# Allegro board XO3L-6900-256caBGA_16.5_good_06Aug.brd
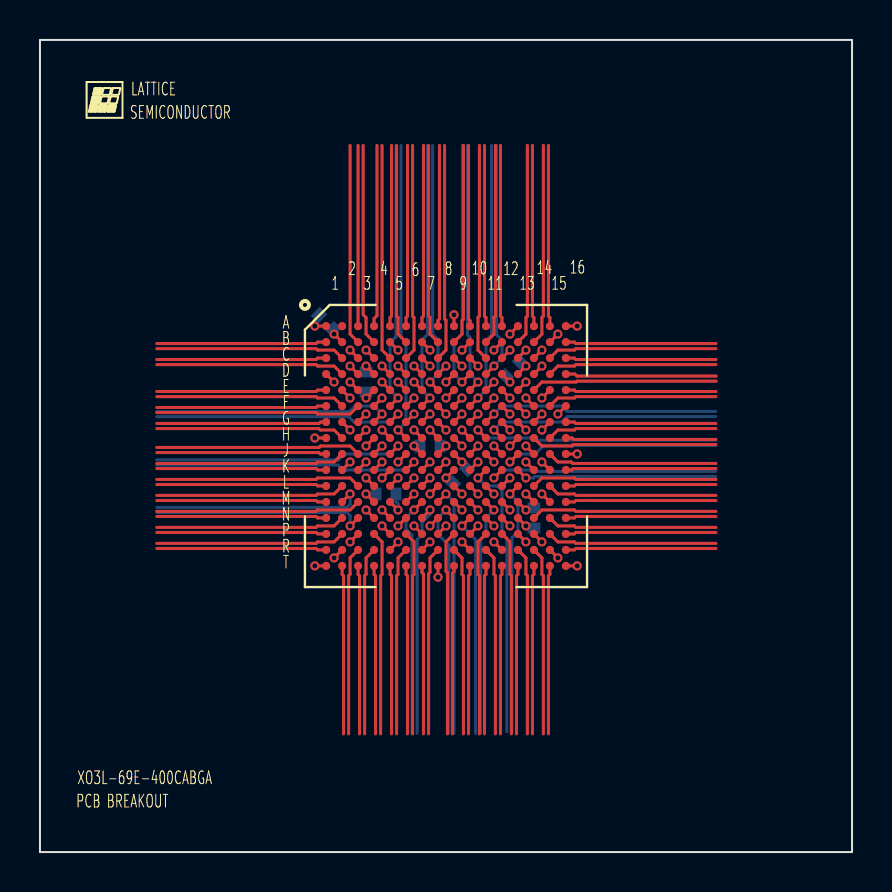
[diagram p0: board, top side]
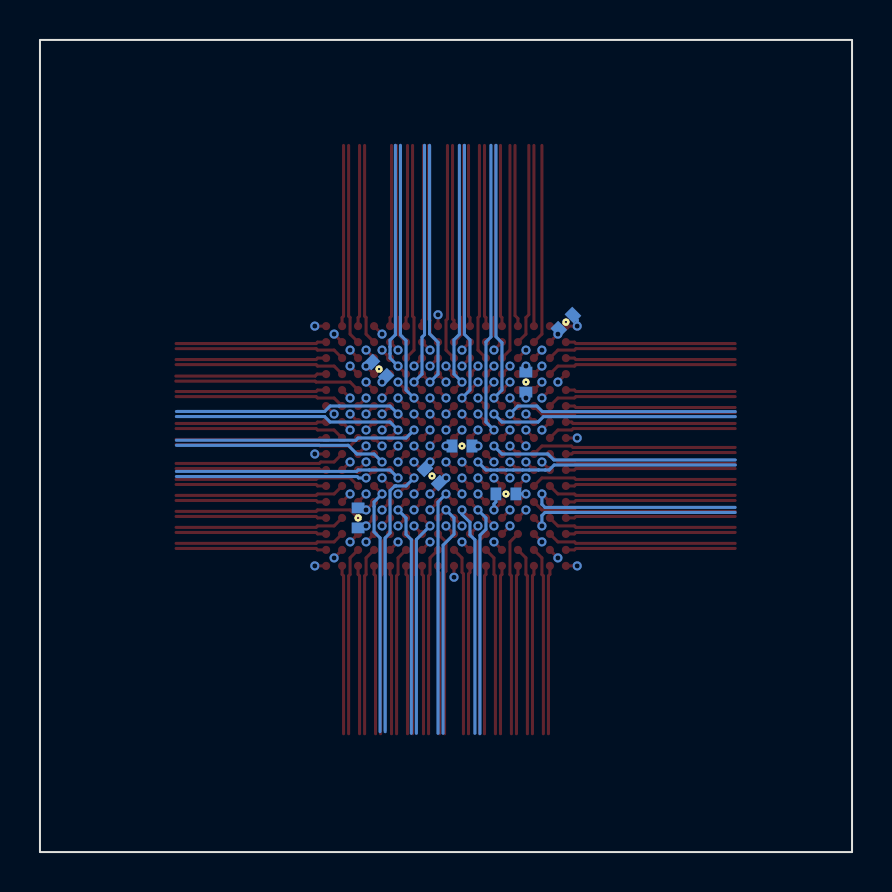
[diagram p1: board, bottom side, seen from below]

Outline 40.64 x 40.64 mm; copper layers: TOP, L2_GND, L3_SIGNAL, L4_SIGNAL, L5_PWR, BOTTOM. Coordinates in mm from the lower left corner of the outline.
Outline path: rectangle 0,0 40.64,40.64

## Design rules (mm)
net group CDPB4: nets PB4C PB4D
net group CDPB13: nets PB13C PB13D
net group CDPB18: nets PB18C PB18D
net group CDPB26: nets PB26C PB26D
net group CDPB31: nets PB31C PB31D
net group CDPB38: nets PB38C PB38D
net group CDPL2: nets PL2C PL2D
net group CDPL4: nets PL4C PL4D
net group CDPL6: nets PL6C PL6D
net group CDPL7: nets PL7C PL7D
net group CDPL9: nets PL9C PL9D
net group CDPL10: nets PL10C PL10D
net group CDPL15: nets PL15C PL15D
net group CDPL16: nets PL16C PL16D
net group CDPL19: nets PL19C PL19D
net group CDPL21: nets PL21C PL21D
net group CDPL23: nets PL23C PL23D
net group CDPL25: nets PL25C PL25D
net group CDPR2: nets PR2C PR2D
net group CDPR4: nets PR4C PR4D
net group CDPR6: nets PR6C PR6D
net group CDPR7: nets PR7C PR7D
net group CDPR10: nets PR10C PR10D
net group CDPR11: nets PR11C PR11D
net group CDPR16: nets PR16C PR16D
net group CDPR17: nets PR17C PR17D
net group CDPR19: nets PR19C PR19D
net group CDPR21: nets PR21C PR21D
net group CDPR23: nets PR23C PR23D
net group CDPR25: nets PR25C PR25D
net group CDPT14: nets PT14C PT14D
net group CDPT17: nets PT17C PT17D
net group CDPT22: nets PT22C PT22D
net group CDPT27: nets PT27C PT27D
net group CDPT36: nets PT36C PT36D
net group PB4: nets PB4A PB4B
net group PB6: nets PB6A PB6B
net group PB7: nets PB7A PB7B
net group PB9: nets PB9A PB9B
net group PB10: nets PB10A PB10B
net group PB12: nets PB12A PB12B
net group PB13: nets PB13A PB13B
net group PB15: nets PB15A PB15B
net group PB16: nets PB16A PB16B
net group PB18: nets PB18A PB18B
net group PB21: nets PB21A PB21B
net group PB23: nets PB23A PB23B
net group PB26: nets PB26A PB26B
net group PB28: nets PB28A PB28B
net group PB29: nets PB29A PB29B
net group PB31: nets PB31A PB31B
net group PB34: nets PB34A PB34B
net group PB35: nets PB35A PB35B
net group PB37: nets PB37A PB37B
net group PB38: nets PB38A PB38B
net group PL3: nets PL3A PL3B
net group PL4: nets PL4A PL4B
net group PL6: nets PL6A PL6B
net group PL8: nets PL8A PL8B
net group PL9: nets PL9A PL9B
net group PL10: nets PL10A PL10B
net group PL11: nets PL11A PL11B
net group PL12: nets PL12A PL12B
net group PL15: nets PL15A PL15B
net group PL17: nets PL17A PL17B
net group PL19: nets PL19A PL19B
net group PL22: nets PL22A PL22B
net group PL24: nets PL24A PL24B
net group PL25: nets PL25A PL25B
net group PR2: nets PR2A PR2B
net group PR3: nets PR3A PR3B
net group PR5: nets PR5A PR5B
net group PR7: nets PR7A PR7B
net group PR9: nets PR9A PR9B
net group PR11: nets PR11A PR11B
net group PR12: nets PR12A PR12B
net group PR15: nets PR15A PR15B
net group PR16: nets PR16A PR16B
net group PR17: nets PR17A PR17B
net group PR18: nets PR18A PR18B
net group PR21: nets PR21A PR21B
net group PR23: nets PR23A PR23B
net group PR24: nets PR24A PR24B
net group PT9: nets PT9A PT9B
net group PT10: nets PT10A PT10B
net group PT11: nets PT11A PT11B
net group PT12: nets PT12A PT12B
net group PT14: nets PT14A PT14B
net group PT15: nets PT15A PT15B
net group PT16: nets PT16A PT16B
net group PT17: nets PT17A PT17B
net group PT18: nets PT18A PT18B
net group PT21: nets PT21A PT21B
net group PT22: nets PT22A PT22B
net group PT25: nets PT25A PT25B
net group PT26: nets PT26A PT26B
net group PT27: nets PT27A PT27B
net group PT28: nets PT28A PT28B
net group PT32: nets PT32A PT32B
net group PT33: nets PT33A PT33B
net group PT34: nets PT34A PT34B
net group PT35: nets PT35A PT35B
net group PT36: nets PT36A PT36B

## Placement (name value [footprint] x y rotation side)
BGA  -  [BGA256C80P16X16_1400X1400X17-1]  20.32 20.32 270 top
C1  VAL  [C0402]  16.32 23.52 90 bottom
C2  VAL  [C0402]  23.67 24.17 45 bottom
C3  VAL  [C0402]  14.32 26.52 315 bottom
C4  VAL  [C0402]  19.52 20.32 0 bottom
C5  VAL  [C0402]  24.72 16.72 270 bottom
C6  VAL  [C0402]  21.02 18.82 45 bottom
C7  VAL  [C0402]  17.32 17.92 0 bottom
NOREF  -  []  24.69 13 0 top

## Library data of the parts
BGA = BGA256C80P16X16_1400X1400X17-1
C1-C7 = C0402: User Part Number: UPN; Tolerance: TOL

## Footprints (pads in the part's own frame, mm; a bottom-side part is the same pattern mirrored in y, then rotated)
BGA256C80P16X16_1400X1400X17-1
  round 0.406 smd: A1(-6,-6) A2(-6,-5.2) A3(-6,-4.4) A4(-6,-3.6) A5(-6,-2.8) A6(-6,-2) A7(-6,-1.2) A8(-6,-0.4) A9(-6,0.4) A10(-6,1.2) A11(-6,2) A12(-6,2.8) A13(-6,3.6) A14(-6,4.4) A15(-6,5.2) A16(-6,6) B1(-5.2,-6) B2(-5.2,-5.2) B3(-5.2,-4.4) B4(-5.2,-3.6) B5(-5.2,-2.8) B6(-5.2,-2) B7(-5.2,-1.2) B8(-5.2,-0.4) B9(-5.2,0.4) B10(-5.2,1.2) B11(-5.2,2) B12(-5.2,2.8) B13(-5.2,3.6) B14(-5.2,4.4) B15(-5.2,5.2) B16(-5.2,6) C1(-4.4,-6) C2(-4.4,-5.2) C3(-4.4,-4.4) C4(-4.4,-3.6) C5(-4.4,-2.8) C6(-4.4,-2) C7(-4.4,-1.2) C8(-4.4,-0.4) C9(-4.4,0.4) C10(-4.4,1.2) C11(-4.4,2) C12(-4.4,2.8) C13(-4.4,3.6) C14(-4.4,4.4) C15(-4.4,5.2) C16(-4.4,6) D1(-3.6,-6) D2(-3.6,-5.2) D3(-3.6,-4.4) D4(-3.6,-3.6) D5(-3.6,-2.8) D6(-3.6,-2) D7(-3.6,-1.2) D8(-3.6,-0.4) D9(-3.6,0.4) D10(-3.6,1.2) D11(-3.6,2) D12(-3.6,2.8) D13(-3.6,3.6) D14(-3.6,4.4) D15(-3.6,5.2) D16(-3.6,6) E1(-2.8,-6) E2(-2.8,-5.2) E3(-2.8,-4.4) E4(-2.8,-3.6) E5(-2.8,-2.8) E6(-2.8,-2) E7(-2.8,-1.2) E8(-2.8,-0.4) E9(-2.8,0.4) E10(-2.8,1.2) E11(-2.8,2) E12(-2.8,2.8) E13(-2.8,3.6) E14(-2.8,4.4) E15(-2.8,5.2) E16(-2.8,6) F1(-2,-6) F2(-2,-5.2) F3(-2,-4.4) F4(-2,-3.6) F5(-2,-2.8) F6(-2,-2) F7(-2,-1.2) F8(-2,-0.4) F9(-2,0.4) F10(-2,1.2) F11(-2,2) F12(-2,2.8) F13(-2,3.6) F14(-2,4.4) F15(-2,5.2) F16(-2,6) G1(-1.2,-6) G2(-1.2,-5.2) G3(-1.2,-4.4) G4(-1.2,-3.6) G5(-1.2,-2.8) G6(-1.2,-2) G7(-1.2,-1.2) G8(-1.2,-0.4) G9(-1.2,0.4) G10(-1.2,1.2) G11(-1.2,2) G12(-1.2,2.8) G13(-1.2,3.6) G14(-1.2,4.4) G15(-1.2,5.2) G16(-1.2,6) H1(-0.4,-6) H2(-0.4,-5.2) H3(-0.4,-4.4) H4(-0.4,-3.6) H5(-0.4,-2.8) H6(-0.4,-2) H7(-0.4,-1.2) H8(-0.4,-0.4) H9(-0.4,0.4) H10(-0.4,1.2) H11(-0.4,2) H12(-0.4,2.8) H13(-0.4,3.6) H14(-0.4,4.4) H15(-0.4,5.2) H16(-0.4,6) J1(0.4,-6) J2(0.4,-5.2) J3(0.4,-4.4) J4(0.4,-3.6) J5(0.4,-2.8) J6(0.4,-2) J7(0.4,-1.2) J8(0.4,-0.4) J9(0.4,0.4) J10(0.4,1.2) J11(0.4,2) J12(0.4,2.8) J13(0.4,3.6) J14(0.4,4.4) J15(0.4,5.2) J16(0.4,6) K1(1.2,-6) K2(1.2,-5.2) K3(1.2,-4.4) K4(1.2,-3.6) K5(1.2,-2.8) K6(1.2,-2) K7(1.2,-1.2) K8(1.2,-0.4) K9(1.2,0.4) K10(1.2,1.2) K11(1.2,2) K12(1.2,2.8) K13(1.2,3.6) K14(1.2,4.4) K15(1.2,5.2) K16(1.2,6) L1(2,-6) L2(2,-5.2) L3(2,-4.4) L4(2,-3.6) L5(2,-2.8) L6(2,-2) L7(2,-1.2) L8(2,-0.4) L9(2,0.4) L10(2,1.2) L11(2,2) L12(2,2.8) L13(2,3.6) L14(2,4.4) L15(2,5.2) L16(2,6) M1(2.8,-6) M2(2.8,-5.2) M3(2.8,-4.4) M4(2.8,-3.6) M5(2.8,-2.8) M6(2.8,-2) M7(2.8,-1.2) M8(2.8,-0.4) M9(2.8,0.4) M10(2.8,1.2) M11(2.8,2) M12(2.8,2.8) M13(2.8,3.6) M14(2.8,4.4) M15(2.8,5.2) M16(2.8,6) N1(3.6,-6) N2(3.6,-5.2) N3(3.6,-4.4) N4(3.6,-3.6) N5(3.6,-2.8) N6(3.6,-2) N7(3.6,-1.2) N8(3.6,-0.4) N9(3.6,0.4) N10(3.6,1.2) N11(3.6,2) N12(3.6,2.8) N13(3.6,3.6) N14(3.6,4.4) N15(3.6,5.2) N16(3.6,6) P1(4.4,-6) P2(4.4,-5.2) P3(4.4,-4.4) P4(4.4,-3.6) P5(4.4,-2.8) P6(4.4,-2) P7(4.4,-1.2) P8(4.4,-0.4) P9(4.4,0.4) P10(4.4,1.2) P11(4.4,2) P12(4.4,2.8) P13(4.4,3.6) P14(4.4,4.4) P15(4.4,5.2) P16(4.4,6) R1(5.2,-6) R2(5.2,-5.2) R3(5.2,-4.4) R4(5.2,-3.6) R5(5.2,-2.8) R6(5.2,-2) R7(5.2,-1.2) R8(5.2,-0.4) R9(5.2,0.4) R10(5.2,1.2) R11(5.2,2) R12(5.2,2.8) R13(5.2,3.6) R14(5.2,4.4) R15(5.2,5.2) R16(5.2,6) T1(6,-6) T2(6,-5.2) T3(6,-4.4) T4(6,-3.6) T5(6,-2.8) T6(6,-2) T7(6,-1.2) T8(6,-0.4) T9(6,0.4) T10(6,1.2) T11(6,2) T12(6,2.8) T13(6,3.6) T14(6,4.4) T15(6,5.2) T16(6,6)
C0402
  rect 0.54x0.64 smd: 1(-0.5,0) 2(0.5,0)

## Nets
GND: BGA.B2 BGA.B15 BGA.C3 BGA.C14 BGA.D4 BGA.D13 BGA.E5 BGA.E12 BGA.F6 BGA.F11 BGA.H8 BGA.H9 BGA.J8 BGA.J9 BGA.L6 BGA.L11 BGA.M5 BGA.M12 BGA.N4 BGA.N13 BGA.P3 BGA.P14 BGA.R2 BGA.R15 C1.2 C2.2 C3.2 C4.2 C5.2 C6.2 C7.2
VCC: BGA.A1 BGA.A16 BGA.G7 BGA.G10 BGA.K7 BGA.K10 BGA.T1 BGA.T16 C3.1
VCCIO0: BGA.D5 BGA.D12 BGA.G8 BGA.G9 C2.1
VCCIO1: BGA.E13 BGA.H10 BGA.J10 BGA.M13 C5.1
VCCIO2: BGA.K8 BGA.K9 BGA.N5 BGA.N12 C6.1
VCCIO3: BGA.M4 C7.1
VCCIO4: BGA.H7 BGA.J7 C4.1
VCCIO5: BGA.E4 C1.1
NC: BGA.A2
PB4A: BGA.P4
PB4B: BGA.T4
PB4C: BGA.T2
PB4D: BGA.R3
PB6A: BGA.R5
PB6B: BGA.P5
PB7A: BGA.T3
PB7B: BGA.R4
PB9A: BGA.T5
PB9B: BGA.R6
PB10A: BGA.N6
PB10B: BGA.L7
PB12A: BGA.P6
PB12B: BGA.T6
PB13A: BGA.R7
PB13B: BGA.P7
PB13C: BGA.M7
PB13D: BGA.N7
PB15A: BGA.M6
PB15B: BGA.L8
PB16A: BGA.T7
PB16B: BGA.R8
PB18A: BGA.P8
PB18B: BGA.T8
PB18C: BGA.N8
PB18D: BGA.L9
PB21A: BGA.M8
PB21B: BGA.N9
PB23A: BGA.T9
PB23B: BGA.P9
PB26A: BGA.R9
PB26B: BGA.T10
PB26C: BGA.M9
PB26D: BGA.L10
PB28A: BGA.N10
PB28B: BGA.M11
PB29A: BGA.P10
PB29B: BGA.R10
PB31A: BGA.T11
PB31B: BGA.P11
PB31C: BGA.M10
PB31D: BGA.N11
PB34A: BGA.R13
PB34B: BGA.T14
PB35A: BGA.R11
PB35B: BGA.T12
PB37A: BGA.P12
PB37B: BGA.T13
PB38A: BGA.R12
PB38B: BGA.P13
PB38C: BGA.T15
PB38D: BGA.R14
PL2C: BGA.B1
PL2D: BGA.C2
PL3A: BGA.D3
PL3B: BGA.D1
PL4A: BGA.E2
PL4B: BGA.E3
PL4C: BGA.C1
PL4D: BGA.D2
PL6A: BGA.E1
PL6B: BGA.F2
PL6C: BGA.F4
PL6D: BGA.G6
PL7C: BGA.G5
PL7D: BGA.G4
PL8A: BGA.F3
PL8B: BGA.F1
PL9A: BGA.G2
PL9B: BGA.G3
PL9C: BGA.F5
PL9D: BGA.H6
PL10A: BGA.G1
PL10B: BGA.H2
PL10C: BGA.H4
PL10D: BGA.J6
PL11A: BGA.H3
PL11B: BGA.H1
PL12A: BGA.J1
PL12B: BGA.J3
PL15A: BGA.J2
PL15B: BGA.K1
PL15C: BGA.H5
PL15D: BGA.J4
PL16C: BGA.J5
PL16D: BGA.K6
PL17A: BGA.K3
PL17B: BGA.K2
PL19A: BGA.L1
PL19B: BGA.L3
PL19C: BGA.K4
PL19D: BGA.L5
PL21C: BGA.K5
PL21D: BGA.L4
PL22A: BGA.L2
PL22B: BGA.M1
PL23C: BGA.N2
PL23D: BGA.P1
PL24A: BGA.M3
PL24B: BGA.N1
PL25A: BGA.M2
PL25B: BGA.N3
PL25C: BGA.R1
PL25D: BGA.P2
PR2A: BGA.D14
PR2B: BGA.E15
PR2C: BGA.C15
PR2D: BGA.B16
PR3A: BGA.D16
PR3B: BGA.E14
PR4C: BGA.C16
PR4D: BGA.D15
PR5A: BGA.E16
PR5B: BGA.F15
PR6C: BGA.F13
PR6D: BGA.G12
PR7A: BGA.F14
PR7B: BGA.F16
PR7C: BGA.F12
PR7D: BGA.G13
PR9A: BGA.G15
PR9B: BGA.G14
PR10C: BGA.G11
PR10D: BGA.H12
PR11A: BGA.G16
PR11B: BGA.H15
PR11C: BGA.H13
PR11D: BGA.J12
PR12A: BGA.H14
PR12B: BGA.H16
PR15A: BGA.J16
PR15B: BGA.J14
PR16A: BGA.J15
PR16B: BGA.K16
PR16C: BGA.H11
PR16D: BGA.J13
PR17A: BGA.K14
PR17B: BGA.K15
PR17C: BGA.J11
PR17D: BGA.L12
PR18A: BGA.L16
PR18B: BGA.L14
PR19C: BGA.K13
PR19D: BGA.K12
PR21A: BGA.L15
PR21B: BGA.M16
PR21C: BGA.K11
PR21D: BGA.L13
PR23A: BGA.M14
PR23B: BGA.M15
PR23C: BGA.N15
PR23D: BGA.P16
PR24A: BGA.N16
PR24B: BGA.N14
PR25C: BGA.P15
PR25D: BGA.R16
PT9A: BGA.C4
PT9B: BGA.B5
PT9C: BGA.B3
PT10A: BGA.A4
PT10B: BGA.C5
PT11A: BGA.A5
PT11B: BGA.B6
PT12A: BGA.A3
PT12B: BGA.B4
PT14A: BGA.D6
PT14B: BGA.E7
PT14C: BGA.C6
PT14D: BGA.A6
PT15A: BGA.B7
PT15B: BGA.C7
PT16A: BGA.E6
PT16B: BGA.D7
PT17A: BGA.F7
PT17B: BGA.E8
PT17C: BGA.A7
PT17D: BGA.B8
PT18A: BGA.C8
PT18B: BGA.A8
PT21A: BGA.D8
PT21B: BGA.E9
PT22A: BGA.F8
PT22B: BGA.D9
PT22C: BGA.A9
PT22D: BGA.C9
PT25A: BGA.B9
PT25B: BGA.A10
PT26A: BGA.F9
PT26B: BGA.E11
PT27A: BGA.D10
PT27B: BGA.E10
PT27C: BGA.C10
PT27D: BGA.B10
PT28A: BGA.A11
PT28B: BGA.C11
PT32A: BGA.F10
PT32B: BGA.D11
PT33A: BGA.B11
PT33B: BGA.A12
PT34A: BGA.B13
PT34B: BGA.A14
PT35A: BGA.C12
PT35B: BGA.B12
PT36A: BGA.B14
PT36B: BGA.A15
PT36C: BGA.A13
PT36D: BGA.C13

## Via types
v1: diameter 0.457, hole 0.254, TOP to BOTTOM, 158 vias

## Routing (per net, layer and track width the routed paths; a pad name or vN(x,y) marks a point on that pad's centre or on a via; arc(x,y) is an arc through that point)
GND: length 16.6
  TOP w0.152: v1(24.32,16.32) BGA.N13 ; v1(22.72,22.72) BGA.F11 ; v1(22.72,17.92) BGA.L11 ; v1(19.52,21.12) BGA.H8 ; v1(16.32,17.12) BGA.N4 ; v1(25.12,25.12) BGA.C14 ; v1(14.72,14.72) BGA.R2 ; v1(17.12,23.52) BGA.E5 ; v1(25.92,25.92) BGA.B15 ; v1(18.72,18.72) BGA.L6 ; v1(15.52,25.12) BGA.C3 ; v1(15.52,15.52) BGA.P3 ; v1(23.52,22.72) BGA.E12 ; v1(21.12,19.52) BGA.J9 ; v1(25.92,14.72) BGA.R15 ; v1(20.32,20.32) BGA.J8 ; v1(21.12,20.32) BGA.H9 ; v1(25.12,15.52) BGA.P14 ; BGA.M5 v1(17.92,17.12) ; v1(16.32,24.32) BGA.D4 ; v1(14.72,25.92) BGA.B2 ; v1(18.72,22.72) BGA.F6 ; v1(24.32,24.32) BGA.D13 ; v1(23.52,17.12) BGA.M12
  BOTTOM w0.152: C7.2 17.82,17.52 17.92,17.43 v1(17.92,17.12) ; C1.2 v1(16.32,24.32) ; C4.2 v1(20.32,20.32) ; v1(24.32,24.32) 24.12,24.52 C2.2 ; C3.2 14.72,26.12 v1(14.72,25.92) ; v1(24.32,16.32) 24.62,16.32 C5.2 ; v1(21.12,19.52) 21.37,19.27 C6.2
VCC: length 5.2
  TOP w0.152: v1(13.75,14.32) BGA.T1 ; v1(26.89,26.32) BGA.A16 ; v1(21.92,19.52) BGA.K10 ; v1(21.92,21.92) BGA.G10 ; v1(13.75,26.32) BGA.A1 ; v1(19.52,21.92) BGA.G7 ; v1(19.52,19.52) BGA.K7 ; v1(26.89,14.32) BGA.T16
  BOTTOM w0.152: v1(13.75,26.32) 13.75,26.62 13.97,26.84 C3.1
VCCIO0: length 2.6
  TOP w0.152: v1(23.52,23.52) BGA.D12 ; v1(20.32,21.12) BGA.G8 ; v1(21.12,21.92) BGA.G9 ; v1(17.12,24.32) BGA.D5
  BOTTOM w0.152: v1(23.52,23.52) 23.32,23.72 C2.1
VCCIO1: length 2.7
  TOP w0.152: v1(24.32,23.52) BGA.E13 ; v1(21.92,20.32) BGA.J10 ; v1(21.12,21.12) BGA.H10 ; v1(24.32,17.12) BGA.M13
  BOTTOM w0.152: C5.1 24.72,17.18 24.66,17.12 v1(24.32,17.12)
VCCIO2: length 2.7
  TOP w0.152: v1(17.12,17.12) BGA.N5 ; BGA.K9 v1(20.32,18.72) ; v1(20.32,19.52) BGA.K8 ; v1(23.52,16.32) BGA.N12
  BOTTOM w0.152: C6.1 20.57,18.47 v1(20.32,18.72)
VCCIO3: length 1.1
  TOP w0.152: BGA.M4 v1(16.32,17.92)
  BOTTOM w0.152: v1(16.32,17.92) C7.1
VCCIO4: length 1.4
  TOP w0.152: v1(18.72,20.32) BGA.J7 ; v1(18.72,21.12) BGA.H7
  BOTTOM w0.152: C4.1 v1(18.72,20.32)
VCCIO5: length 0.9
  TOP w0.152: v1(16.32,22.72) BGA.E4
  BOTTOM w0.152: C1.1 v1(16.32,22.72)
PB4A: length 10.2
  TOP w0.152: BGA.P4 17.12,15.52 17.12,13.89 17.05,13.82 17.05,5.92
PB4B: length 8.4
  TOP w0.152: 16.79,5.92 16.79,13.82 16.72,13.89 BGA.T4
PB4C: length 8.4
  TOP w0.152: 15.19,5.92 15.19,13.82 15.12,13.89 BGA.T2
PB4D: length 9.4
  TOP w0.152: BGA.R3 15.52,14.72 15.52,13.89 15.45,13.82 15.45,5.92
PB6A: length 10.9
  TOP w0.152: v1(17.92,15.52) BGA.R5
  L3_SIGNAL w0.152: v1(17.92,15.52) 17.72,15.72 17.5,15.72 17.27,15.5 17.27,5.97
PB6B: length 11.1
  TOP w0.152: v1(17.12,16.32) BGA.P5
  L3_SIGNAL w0.152: 17.02,5.97 17.02,15.6 17.32,15.9 17.32,16.12 v1(17.12,16.32)
PB7A: length 8.4
  TOP w0.152: 15.99,5.92 15.99,13.82 15.92,13.89 BGA.T3
PB7B: length 9.4
  TOP w0.152: BGA.R4 16.32,14.72 16.32,13.89 16.25,13.82 16.25,5.92
PB9A: length 8.4
  TOP w0.152: 17.59,5.92 17.59,13.82 17.52,13.89 BGA.T5
PB9B: length 9.4
  TOP w0.152: BGA.R6 17.92,14.72 17.92,13.89 17.85,13.82 17.85,5.92
PB10A: length 11.7
  TOP w0.152: v1(17.92,16.32) BGA.N6 v1(17.92,16.32)
  L4_SIGNAL w0.152: 17.77,5.97 17.77,14.92 17.52,15.17 17.52,15.35 17.52,15.92 v1(17.92,16.32)
PB10B: length 14.1
  TOP w0.152: v1(19.52,18.72) BGA.L7
  L4_SIGNAL w0.152: v1(19.52,18.72) BGA.L7 19.12,17.75 18.89,17.52 18.55,17.52 18.32,17.29 18.32,15.17 18.02,14.88 18.02,5.97
PB12A: length 10.2
  TOP w0.152: 18.65,5.92 18.65,13.82 18.72,13.89 18.72,15.52 BGA.P6
PB12B: length 8.4
  TOP w0.152: BGA.T6 18.32,13.89 18.39,13.82 18.39,5.92
PB13A: length 11
  TOP w0.152: v1(19.52,15.52) BGA.R7
  L3_SIGNAL w0.152: 18.81,5.95 18.81,15.43 19.1,15.72 19.32,15.72 v1(19.52,15.52)
PB13B: length 11.2
  TOP w0.152: v1(18.72,16.32) BGA.P7
  L3_SIGNAL w0.152: v1(18.72,16.32) 18.92,16.12 18.92,15.9 18.56,15.54 18.56,5.95
PB13C: length 12.6
  TOP w0.152: v1(18.72,17.12) BGA.M7 v1(18.72,17.12)
  BOTTOM w0.152: 18.62,5.92 18.62,15.85 18.32,16.15 18.32,16.72 v1(18.72,17.12)
PB13D: length 12
  TOP w0.152: v1(19.52,17.12) BGA.N7
  BOTTOM w0.152: 18.87,5.94 18.87,15.63 19.12,15.87 19.12,16.5 19.52,16.9 v1(19.52,17.12)
PB15A: length 14.3
  TOP w0.152: v1(18.72,17.92) BGA.M6 v1(18.72,17.92)
  L3_SIGNAL w0.152: v1(18.72,17.92) 17.17,17.92 16.77,17.52 15.27,17.52 14.98,17.82 5.82,17.82
PB15B: length 15.2
  TOP w0.152: v1(19.52,17.92) BGA.L8 v1(19.52,17.92)
  L3_SIGNAL w0.152: v1(19.52,17.92) 19.12,18.32 18.55,18.32 18.41,18.17 16.87,18.17 16.72,18.32 16.15,18.32 15.22,18.32 14.97,18.07 5.82,18.07
PB16A: length 8.4
  TOP w0.152: BGA.T7 19.12,13.99 19.19,13.92 19.19,5.92
PB16B: length 9.4
  TOP w0.152: 19.45,5.92 19.45,13.92 19.52,14 19.52,14.72 BGA.R8
PB18A: length 11.4
  TOP w0.152: v1(20.32,16.32) BGA.P8
  L3_SIGNAL w0.152: 21.01,5.95 21.01,14.69 20.59,15.12 20.42,15.12 20.29,15.14 20.16,15.31 v1(20.32,16.32)
PB18B: length 11.1
  TOP w0.152: v1(19.92,13.75) BGA.T8
  L3_SIGNAL w0.152: 20.76,5.95 20.76,14.59 20.48,14.86 20.4,14.86 20.25,14.89 20.08,14.76 v1(19.92,13.75)
PB18C: length 11.2
  TOP w0.152: v1(19.52,16.32) BGA.N8
  L4_SIGNAL w0.152: v1(19.52,16.32) 19.03,15.83 19.03,14.91 19.23,14.72 19.23,5.96
PB18D: length 13.5
  TOP w0.152: v1(21.12,17.92) BGA.L9
  L4_SIGNAL w0.152: 19.48,5.96 19.48,14.7 19.92,15.14 19.92,17.13 19.92,17.29 20.15,17.52 20.72,17.52 v1(21.12,17.92)
PB21A: length 12.7
  TOP w0.152: v1(20.32,17.92) BGA.M8
  BOTTOM w0.152: v1(20.32,17.92) 20.72,17.52 20.72,5.94
PB21B: length 12.1
  TOP w0.152: v1(20.32,17.12) BGA.N9
  BOTTOM w0.152: v1(20.32,17.12) 19.92,16.72 19.92,15.9 20.47,15.36 20.47,5.94
PB23A: length 8.4
  TOP w0.152: 20.65,5.92 20.65,13.96 20.72,14.04 BGA.T9
PB23B: length 10.2
  TOP w0.152: BGA.P9 20.32,15.52 20.32,14.05 20.39,13.98 20.39,5.92
PB26A: length 9.4
  TOP w0.152: BGA.R9 21.12,14.72 21.12,13.89 21.19,13.82 21.19,5.92
PB26B: length 8.4
  TOP w0.152: 21.45,5.92 21.45,13.82 21.52,13.89 BGA.T10
PB26C: length 12
  TOP w0.152: v1(21.12,17.12) BGA.M9
  L4_SIGNAL w0.152: v1(21.12,17.12) 20.72,16.72 20.72,14.99 20.91,14.79 20.91,5.95
PB26D: length 12.8
  TOP w0.152: v1(21.92,17.92) BGA.L10
  L4_SIGNAL w0.152: 21.17,5.95 21.17,14.77 21.52,15.13 21.52,17.52 v1(21.92,17.92)
PB28A: length 11.2
  TOP w0.152: v1(21.12,16.32) BGA.N10
  BOTTOM w0.152: v1(21.12,16.32) 21.8,15.64 21.8,5.94
PB28B: length 12
  TOP w0.152: v1(22.72,17.12) BGA.M11
  BOTTOM w0.152: v1(22.72,17.12) 22.32,16.72 22.32,15.9 22.06,15.63 22.06,5.94
PB29A: length 11.1
  TOP w0.152: v1(21.92,16.32) BGA.P10
  L3_SIGNAL w0.152: v1(21.92,16.32) 21.72,16.12 21.72,15.9 22.03,15.59 22.03,5.95
PB29B: length 10.9
  TOP w0.152: v1(21.12,15.52) BGA.R10
  L3_SIGNAL w0.152: v1(21.12,15.52) 21.32,15.72 21.54,15.72 21.78,15.48 21.78,5.95
PB31A: length 8.4
  TOP w0.152: 22.25,5.92 22.25,13.82 22.32,13.89 BGA.T11
PB31B: length 10.2
  TOP w0.152: BGA.P11 21.92,15.52 21.92,13.89 21.99,13.82 21.99,5.92
PB31C: length 12
  TOP w0.152: v1(21.92,17.12) BGA.M10
  L4_SIGNAL w0.152: 22.63,5.96 22.63,14.9 22.32,15.21 22.32,16.72 v1(21.92,17.12)
PB31D: length 11.3
  TOP w0.152: v1(22.72,16.32) BGA.N11
  L4_SIGNAL w0.152: 22.88,5.96 22.88,14.89 23.2,15.21 23.2,15.84 v1(22.72,16.32)
PB34A: length 9.4
  TOP w0.152: BGA.R13 24.32,14.72 24.32,13.89 24.39,13.82 24.39,5.92
PB34B: length 8.4
  TOP w0.152: 24.65,5.92 24.65,13.82 24.72,13.89 BGA.T14
PB35A: length 9.4
  TOP w0.152: 22.79,5.92 22.79,13.82 22.72,13.89 22.72,14.72 BGA.R11
PB35B: length 8.4
  TOP w0.152: BGA.T12 23.12,13.89 23.05,13.82 23.05,5.92
PB37A: length 10.2
  TOP w0.152: BGA.P12 23.52,15.52 23.52,13.89 23.59,13.82 23.59,5.92
PB37B: length 8.4
  TOP w0.152: 23.85,5.92 23.85,13.82 23.92,13.89 BGA.T13
PB38A: length 10.7
  TOP w0.152: v1(22.72,15.52) BGA.R12
  L3_SIGNAL w0.152: v1(22.72,15.52) 23.24,15.52 23.39,15.37 23.39,5.95
PB38B: length 10.7
  TOP w0.152: v1(24.32,15.52) BGA.P13
  L3_SIGNAL w0.152: 23.65,5.95 23.65,15.37 23.8,15.52 v1(24.32,15.52)
PB38C: length 8.4
  TOP w0.152: 25.45,5.92 25.45,13.82 25.52,13.89 BGA.T15
PB38D: length 9.4
  TOP w0.152: 25.19,5.92 25.19,13.82 25.12,13.89 25.12,14.72 BGA.R14
PL2C: length 8.5
  TOP w0.152: BGA.B1 13.89,25.52 13.82,25.45 5.85,25.45
PL2D: length 9.5
  TOP w0.152: 5.85,25.19 13.82,25.19 13.89,25.12 14.72,25.12 BGA.C2
PL3A: length 10.4
  TOP w0.152: v1(15.52,24.32) BGA.D3
  L3_SIGNAL w0.152: v1(15.52,24.32) 15.32,24.12 15.1,24.12 14.75,24.47 5.87,24.47
PL3B: length 10.2
  TOP w0.152: v1(14.72,23.52) BGA.D1
  L3_SIGNAL w0.152: 5.87,24.21 14.65,24.21 14.92,23.94 14.92,23.72 v1(14.72,23.52)
PL4A: length 10.2
  TOP w0.152: v1(15.52,22.72) BGA.E2
  L3_SIGNAL w0.152: 5.85,22.72 15.07,22.72 15.08,22.72 v1(15.52,22.72)
PL4B: length 10.5
  TOP w0.152: v1(15.52,23.52) BGA.E3
  L3_SIGNAL w0.152: v1(15.52,23.52) 14.97,22.97 5.85,22.97
PL4C: length 8.5
  TOP w0.152: BGA.C1 13.89,24.72 13.82,24.65 5.85,24.65
PL4D: length 9.5
  TOP w0.152: 5.85,24.39 13.82,24.39 13.89,24.32 14.72,24.32 BGA.D2
PL6A: length 8.5
  TOP w0.152: 5.85,23.05 13.82,23.05 13.89,23.12 BGA.E1
PL6B: length 9.5
  TOP w0.152: BGA.F2 14.72,22.72 13.89,22.72 13.82,22.79 5.85,22.79
PL6C: length 12.1
  TOP w0.152: v1(17.12,22.72) BGA.F4
  L4_SIGNAL w0.152: v1(17.12,22.72) 16.72,23.12 15.04,23.12 14.79,22.87 5.85,22.87
PL6D: length 13.7
  TOP w0.152: v1(18.72,21.92) BGA.G6
  L4_SIGNAL w0.152: 5.85,22.61 14.84,22.61 15.13,22.32 18.32,22.32 v1(18.72,21.92)
PL7C: length 12.9
  TOP w0.152: v1(17.92,21.92) BGA.G5
  BOTTOM w0.152: 5.84,21.79 15.44,21.79 15.71,21.52 BGA.G5 v1(17.92,21.92)
PL7D: length 12.1
  TOP w0.152: v1(17.12,21.92) BGA.G4
  BOTTOM w0.152: v1(17.12,21.92) 16.72,22.32 15.77,22.32 15.49,22.04 5.84,22.04
PL8A: length 10.3
  TOP w0.152: 5.85,21.99 13.82,21.99 13.89,21.92 15.52,21.92 BGA.F3
PL8B: length 8.5
  TOP w0.152: BGA.F1 13.89,22.32 13.82,22.25 5.85,22.25
PL9A: length 11.1
  TOP w0.152: v1(15.52,21.12) BGA.G2
  L3_SIGNAL w0.152: 5.85,21.87 15.39,21.87 15.72,21.54 15.72,21.32 v1(15.52,21.12)
PL9B: length 11.3
  TOP w0.152: v1(16.32,21.92) BGA.G3
  L3_SIGNAL w0.152: v1(16.32,21.92) 16.12,21.72 15.9,21.72 15.5,22.12 5.85,22.12
PL9C: length 13.5
  TOP w0.152: v1(17.92,22.72) BGA.F5
  BOTTOM w0.152: 17.82,35.37 17.82,25.79 17.52,25.49 17.52,23.12 v1(17.92,22.72)
PL9D: length 15.1
  TOP w0.152: v1(17.92,21.12) BGA.H6
  BOTTOM w0.152: 18.07,35.37 18.07,25.78 18.32,25.53 18.32,21.52 v1(17.92,21.12)
PL10A: length 8.5
  TOP w0.152: 5.85,21.45 13.96,21.45 14.04,21.52 BGA.G1
PL10B: length 9.5
  TOP w0.152: BGA.H2 14.72,21.12 14.03,21.12 13.96,21.19 5.85,21.19
PL10C: length 11.1
  TOP w0.152: v1(16.32,20.32) BGA.H4
  L4_SIGNAL w0.152: 5.85,20.17 15.75,20.17 15.89,20.32 v1(16.32,20.32)
PL10D: length 12.8
  TOP w0.152: v1(17.92,19.52) BGA.J6
  L4_SIGNAL w0.152: 5.82,19.92 17.52,19.92 v1(17.92,19.52)
PL11A: length 11.4
  TOP w0.152: v1(16.32,21.12) BGA.H3
  L3_SIGNAL w0.152: v1(16.32,21.12) 15.72,20.52 14.27,20.52 14.07,20.32 13.47,20.32 13.33,20.47 5.85,20.47
PL11B: length 8.5
  TOP w0.152: v1(13.75,20.72) BGA.H1
  L3_SIGNAL w0.152: 5.84,20.72 v1(13.75,20.72)
PL12A: length 8.5
  TOP w0.152: BGA.J1 14.03,19.92 13.96,19.99 5.85,19.99
PL12B: length 10.3
  TOP w0.152: BGA.J3 15.52,20.32 14.04,20.32 13.97,20.25 5.85,20.25
PL15A: length 9.5
  TOP w0.152: 5.85,19.45 13.82,19.45 13.89,19.52 14.72,19.52 BGA.J2
PL15B: length 8.5
  TOP w0.152: BGA.K1 13.89,19.12 13.82,19.19 5.85,19.19
PL15C: length 12.1
  TOP w0.152: v1(17.12,21.12) BGA.H5
  L4_SIGNAL w0.152: 5.85,21.37 14.46,21.37 14.61,21.52 16.72,21.52 v1(17.12,21.12)
PL15D: length 12.2
  TOP w0.152: v1(17.12,20.32) BGA.J4
  L4_SIGNAL w0.152: v1(17.12,20.32) 16.72,20.72 14.86,20.72 14.46,21.12 5.85,21.12
PL16C: length 12.9
  TOP w0.152: v1(17.92,20.32) BGA.J5
  BOTTOM w0.152: v1(17.92,20.32) BGA.J5 15.22,19.92 14.92,19.62 5.84,19.62
PL16D: length 13.7
  TOP w0.152: v1(18.72,19.52) BGA.K6
  BOTTOM w0.152: 5.84,19.37 14.91,19.37 15.16,19.12 15.35,19.12 16.15,19.12 16.95,19.12 17.75,19.12 BGA.K6 v1(18.72,19.52)
PL17A: length 11.3
  TOP w0.152: v1(16.32,19.52) BGA.K3
  L3_SIGNAL w0.152: 5.85,19.77 15.21,19.77 15.4,19.97 15.87,19.97 v1(16.32,19.52)
PL17B: length 10.2
  TOP w0.152: v1(15.52,19.52) BGA.K2
  L3_SIGNAL w0.152: 5.85,19.52 v1(15.52,19.52)
PL19A: length 8.5
  TOP w0.152: BGA.L1 13.89,18.32 13.82,18.39 5.85,18.39
PL19B: length 10.3
  TOP w0.152: BGA.L3 15.52,18.72 13.89,18.72 13.82,18.65 5.85,18.65
PL19C: length 12.1
  TOP w0.152: v1(17.12,19.52) BGA.K4
  L4_SIGNAL w0.152: 5.85,18.92 15.77,18.92 15.97,19.12 BGA.K4 v1(17.12,19.52)
PL19D: length 12.9
  TOP w0.152: v1(17.92,18.72) BGA.L5
  L4_SIGNAL w0.152: 5.85,18.67 15.78,18.67 16.12,18.32 BGA.L5 v1(17.92,18.72)
PL21C: length 12
  TOP w0.152: v1(17.12,18.72) BGA.K5
  L3_SIGNAL w0.152: v1(17.12,18.72) 16.72,19.12 15.92,19.12 15.83,19.02 5.87,19.02
PL21D: length 11.1
  TOP w0.152: v1(16.32,18.72) BGA.L4
  L3_SIGNAL w0.152: v1(16.32,18.72) 15.92,18.72 15.87,18.77 5.85,18.77
PL22A: length 9.5
  TOP w0.152: 5.85,17.85 13.82,17.85 13.89,17.92 14.72,17.92 BGA.L2
PL22B: length 8.5
  TOP w0.152: BGA.M1 13.89,17.52 13.82,17.59 5.85,17.59
PL23C: length 9.5
  TOP w0.152: BGA.N2 14.72,16.32 13.89,16.32 13.82,16.25 5.85,16.25
PL23D: length 8.5
  TOP w0.152: BGA.P1 13.89,15.92 13.82,15.99 5.85,15.99
PL24A: length 10.3
  TOP w0.152: BGA.M3 15.52,17.12 13.89,17.12 13.82,17.05 5.85,17.05
PL24B: length 8.5
  TOP w0.152: BGA.N1 13.89,16.72 13.82,16.79 5.85,16.79
PL25A: length 10.8
  TOP w0.152: v1(15.52,17.92) BGA.M2
  BOTTOM w0.152: 5.85,17.25 15.37,17.25 15.52,17.4 v1(15.52,17.92)
PL25B: length 10.8
  TOP w0.152: v1(15.52,16.32) BGA.N3
  BOTTOM w0.152: 5.85,16.99 15.37,16.99 15.52,16.84 v1(15.52,16.32)
PL25C: length 8.5
  TOP w0.152: BGA.R1 13.89,15.12 13.82,15.19 5.85,15.19
PL25D: length 9.5
  TOP w0.152: 5.85,15.45 13.82,15.45 13.89,15.52 14.72,15.52 BGA.P2
PR2A: length 9.8
  TOP w0.152: v1(25.12,24.32) BGA.D14
  L3_SIGNAL w0.152: 33.79,23.65 25.27,23.65 25.12,23.8 v1(25.12,24.32)
PR2B: length 9.8
  TOP w0.152: v1(25.12,22.72) BGA.E15
  L3_SIGNAL w0.152: v1(25.12,22.72) 25.12,23.24 25.27,23.39 33.79,23.39
PR2C: length 8.5
  TOP w0.152: BGA.C15 25.92,25.12 26.75,25.12 26.82,25.19 33.83,25.19
PR2D: length 7.5
  TOP w0.152: 33.83,25.45 26.82,25.45 26.75,25.52 BGA.B16
PR3A: length 7.6
  TOP w0.152: 33.84,23.82 26.87,23.82 26.77,23.92 BGA.D16
PR3B: length 9.3
  TOP w0.152: 33.84,23.57 26.87,23.57 26.82,23.52 25.12,23.52 BGA.E14
PR4C: length 7.5
  TOP w0.152: BGA.C16 26.75,24.72 26.82,24.65 33.83,24.65
PR4D: length 8.5
  TOP w0.152: BGA.D15 25.92,24.32 26.75,24.32 26.82,24.39 33.83,24.39
PR5A: length 7.5
  TOP w0.152: 33.83,23.05 26.82,23.05 26.75,23.12 BGA.E16
PR5B: length 8.5
  TOP w0.152: 33.83,22.79 26.82,22.79 26.75,22.72 25.92,22.72 BGA.F15
PR6C: length 10.4
  TOP w0.152: v1(24.32,21.92) BGA.F13
  L4_SIGNAL w0.152: v1(24.32,21.92) 24.72,22.32 25.37,22.32 25.67,22.62 33.82,22.62
PR6D: length 13.4
  TOP w0.152: v1(23.52,21.12) BGA.G12
  L4_SIGNAL w0.152: 33.82,22.87 25.67,22.87 25.42,23.12 23.35,23.12 23.12,22.89 BGA.G12 v1(23.52,21.12)
PR7A: length 10.3
  TOP w0.152: v1(24.32,22.72) BGA.F14
  L3_SIGNAL w0.152: v1(24.32,22.72) BGA.F14 26.09,22.32 26.17,22.25 33.82,22.25
PR7B: length 8.5
  TOP w0.152: v1(25.92,21.92) BGA.F16
  L3_SIGNAL w0.152: v1(25.92,21.92) 26.09,21.92 26.17,21.99 33.82,21.99
PR7C: length 11.2
  TOP w0.152: v1(23.52,21.92) BGA.F12
  L4_SIGNAL w0.152: 33.82,21.22 25.72,21.22 25.42,21.52 23.92,21.52 v1(23.52,21.92)
PR7D: length 10.3
  TOP w0.152: v1(24.32,21.12) BGA.G13
  L4_SIGNAL w0.152: v1(24.32,21.12) 24.55,21.12 24.95,20.72 25.47,20.72 25.72,20.97 33.82,20.97
PR9A: length 9.4
  TOP w0.152: v1(25.12,21.12) BGA.G15
  L3_SIGNAL w0.152: 33.82,20.82 25.86,20.82 25.56,21.12 v1(25.12,21.12)
PR9B: length 9.6
  TOP w0.152: v1(25.12,21.92) BGA.G14
  L3_SIGNAL w0.152: 33.82,21.07 25.97,21.07 25.57,21.47 v1(25.12,21.92)
PR10C: length 11.9
  TOP w0.152: v1(22.72,21.92) BGA.G11
  BOTTOM w0.152: 33.81,22.05 26.39,22.05 26.12,22.32 25.67,22.32 23.12,22.32 v1(22.72,21.92)
PR10D: length 11.9
  TOP w0.152: v1(22.72,21.12) BGA.H12
  BOTTOM w0.152: v1(22.72,21.12) 23.12,21.52 26.12,21.52 26.39,21.79 33.81,21.79
PR11A: length 7.5
  TOP w0.152: 33.83,21.45 26.82,21.45 26.75,21.52 BGA.G16
PR11B: length 8.5
  TOP w0.152: BGA.H15 25.92,21.12 26.75,21.12 26.82,21.19 33.83,21.19
PR11C: length 11.5
  TOP w0.152: v1(23.52,20.32) BGA.H13
  L4_SIGNAL w0.152: v1(23.52,20.32) BGA.H13 24.52,20.72 25.06,20.17 25.67,20.17 26.37,19.47 33.82,19.47
PR11D: length 12.1
  TOP w0.152: v1(22.72,20.32) BGA.J12
  L4_SIGNAL w0.152: v1(22.72,20.32) BGA.J12 25.57,19.92 26.27,19.22 33.82,19.22
PR12A: length 9.3
  TOP w0.152: BGA.H14 25.12,20.32 26.62,20.32 26.7,20.39 33.83,20.39
PR12B: length 7.5
  TOP w0.152: 33.83,20.65 26.71,20.65 26.63,20.72 BGA.H16
PR15A: length 7.5
  TOP w0.152: v1(26.89,19.92) BGA.J16
  L3_SIGNAL w0.152: 33.83,19.92 v1(26.89,19.92)
PR15B: length 10.1
  TOP w0.152: v1(24.32,20.32) BGA.J14
  L3_SIGNAL w0.152: 33.83,20.17 27.36,20.17 27.22,20.32 v1(24.32,20.32)
PR16A: length 8.5
  TOP w0.152: BGA.J15 25.92,19.52 26.59,19.52 26.66,19.45 33.83,19.45
PR16B: length 7.5
  TOP w0.152: BGA.K16 26.61,19.12 26.68,19.19 33.83,19.19
PR16C: length 12.7
  TOP w0.152: v1(21.92,21.12) BGA.H11
  BOTTOM w0.152: v1(21.92,21.12) BGA.H11 24.72,20.72 24.83,20.61 33.81,20.61
PR16D: length 11.2
  TOP w0.152: v1(23.52,19.52) BGA.J13
  BOTTOM w0.152: 33.81,20.35 25.21,20.35 24.78,19.92 BGA.J13 v1(23.52,19.52)
PR17A: length 10.3
  TOP w0.152: v1(24.32,19.52) BGA.K14
  L3_SIGNAL w0.152: v1(24.32,19.52) 24.75,19.09 33.83,19.09
PR17B: length 9.3
  TOP w0.152: v1(25.12,19.52) BGA.K15
  L3_SIGNAL w0.152: v1(25.12,19.52) 25.45,19.52 25.62,19.35 33.83,19.35
PR17C: length 11.9
  TOP w0.152: v1(22.72,19.52) BGA.J11
  L4_SIGNAL w0.152: v1(22.72,19.52) 23.12,19.12 24.71,19.12 24.95,18.89 33.82,18.89
PR17D: length 11.2
  TOP w0.152: v1(23.52,18.72) BGA.L12
  L4_SIGNAL w0.152: 33.82,18.63 24.97,18.63 24.66,18.32 23.92,18.32 v1(23.52,18.72)
PR18A: length 7.5
  TOP w0.152: 33.83,18.39 26.82,18.39 26.75,18.32 BGA.L16
PR18B: length 9.3
  TOP w0.152: 33.83,18.65 26.82,18.65 26.75,18.72 25.12,18.72 BGA.L14
PR19C: length 10.1
  TOP w0.152: v1(24.32,18.72) BGA.K13
  BOTTOM w0.152: v1(24.32,18.72) 24.7,18.72 24.77,18.79 33.81,18.79
PR19D: length 11.9
  TOP w0.152: v1(22.72,18.72) BGA.K12
  BOTTOM w0.152: 33.81,19.05 24.79,19.05 24.72,19.12 24.15,19.12 BGA.K12 v1(22.72,18.72)
PR21A: length 8.5
  TOP w0.152: 33.83,17.85 26.82,17.85 26.75,17.92 25.92,17.92 BGA.L15
PR21B: length 7.5
  TOP w0.152: BGA.M16 26.75,17.52 26.82,17.59 33.83,17.59
PR21C: length 14.2
  TOP w0.152: v1(21.92,18.72) BGA.K11
  BOTTOM w0.152: v1(21.92,18.72) 22.32,18.32 22.82,18.32 22.89,18.32 23.12,18.09 23.12,15.97 23.37,15.72 23.37,6.02
PR21D: length 12.8
  TOP w0.152: v1(23.52,17.92) BGA.L13
  BOTTOM w0.152: v1(23.52,17.92) 23.92,17.52 23.92,17.29 23.92,16.02 23.62,15.72 23.62,6.02
PR23A: length 10.3
  TOP w0.152: v1(24.32,17.92) BGA.M14
  L3_SIGNAL w0.152: 33.83,18.39 24.79,18.39 v1(24.32,17.92)
PR23B: length 9.4
  TOP w0.152: v1(25.12,17.92) BGA.M15
  L3_SIGNAL w0.152: v1(25.12,17.92) 25.44,17.92 25.66,18.14 33.83,18.14
PR23C: length 8.5
  TOP w0.152: 33.83,16.25 26.82,16.25 26.75,16.32 25.92,16.32 BGA.N15
PR23D: length 7.5
  TOP w0.152: 33.83,15.99 26.82,15.99 26.75,15.92 BGA.P16
PR24A: length 7.5
  TOP w0.152: BGA.N16 26.75,16.72 26.82,16.79 33.83,16.79
PR24B: length 9.3
  TOP w0.152: 33.83,17.05 26.82,17.05 26.75,17.12 25.12,17.12 BGA.N14
PR25C: length 8.5
  TOP w0.152: BGA.P15 25.92,15.52 26.75,15.52 26.82,15.45 33.83,15.45
PR25D: length 7.5
  TOP w0.152: BGA.R16 26.75,15.12 26.82,15.19 33.83,15.19
PT9A: length 11.4
  TOP w0.152: v1(16.32,25.12) BGA.C4
  L3_SIGNAL w0.152: 16.99,35.37 16.99,25.27 16.84,25.12 v1(16.32,25.12)
PT9B: length 11.4
  TOP w0.152: v1(17.92,25.12) BGA.B5
  L3_SIGNAL w0.152: 17.25,35.37 17.25,25.27 17.4,25.12 v1(17.92,25.12)
PT9C: length 10
  TOP w0.152: BGA.B3 15.52,25.92 15.52,35.36
PT10A: length 9.1
  TOP w0.152: BGA.A4 16.72,26.7 16.87,26.85 16.87,35.36
PT10B: length 10.8
  TOP w0.152: BGA.C5 17.12,25.12 17.12,35.36
PT11A: length 9.1
  TOP w0.152: 17.59,35.36 17.59,26.82 17.52,26.75 BGA.A5
PT11B: length 10
  TOP w0.152: 17.85,35.36 17.85,26.82 17.92,26.75 17.92,25.92 BGA.B6
PT12A: length 9
  TOP w0.152: BGA.A3 15.92,35.36
PT12B: length 10.1
  TOP w0.152: BGA.B4 16.32,25.92 16.32,26.75 16.17,26.89 16.17,35.36
PT14A: length 11.9
  TOP w0.152: v1(17.92,24.32) BGA.D6
  L4_SIGNAL w0.152: 18.52,35.36 18.52,24.92 v1(17.92,24.32)
PT14B: length 12.7
  TOP w0.152: v1(18.72,23.52) BGA.E7
  L4_SIGNAL w0.152: v1(18.72,23.52) 19.12,23.92 19.12,24.66 18.78,25 18.78,35.36
PT14C: length 10.8
  TOP w0.152: BGA.C6 18.72,25.12 18.72,26.75 18.65,26.82 18.65,35.36
PT14D: length 9.1
  TOP w0.152: 18.39,35.36 18.39,26.82 18.32,26.75 BGA.A6
PT15A: length 10.9
  TOP w0.152: v1(19.52,25.12) BGA.B7
  L3_SIGNAL w0.152: v1(19.52,25.12) 19.52,25.51 19.37,25.66 19.37,35.37
PT15B: length 11.8
  TOP w0.152: v1(19.52,24.32) BGA.C7
  L3_SIGNAL w0.152: v1(19.52,24.32) BGA.C7 19.12,35.37
PT16A: length 12.6
  TOP w0.152: v1(17.92,23.52) BGA.E6
  L3_SIGNAL w0.152: v1(17.92,23.52) 18.32,23.92 18.32,24.65 18.39,24.72 18.39,35.37
PT16B: length 11.6
  TOP w0.152: v1(18.72,24.32) BGA.D7
  L3_SIGNAL w0.152: v1(18.72,24.32) 18.72,24.65 18.65,24.72 18.65,35.37
PT17A: length 13.5
  TOP w0.152: v1(19.52,22.72) BGA.F7
  BOTTOM w0.152: 19.4,35.37 19.4,25.9 19.12,25.63 19.12,23.12 v1(19.52,22.72)
PT17B: length 12.7
  TOP w0.152: v1(19.52,23.52) BGA.E8
  BOTTOM w0.152: 19.65,35.37 19.65,25.91 19.92,25.64 19.92,23.92 v1(19.52,23.52)
PT17C: length 9.1
  TOP w0.152: BGA.A7 19.12,26.75 19.19,26.82 19.19,35.36
PT17D: length 10
  TOP w0.152: BGA.B8 19.52,25.92 19.52,26.75 19.45,26.82 19.45,35.36
PT18A: length 10.8
  TOP w0.152: BGA.C8 20.32,25.12 20.32,26.61 20.25,26.68 20.25,35.36
PT18B: length 9.1
  TOP w0.152: 19.99,35.36 19.99,26.68 19.92,26.6 BGA.A8
PT21A: length 11.7
  TOP w0.152: v1(20.32,24.32) BGA.D8
  L3_SIGNAL w0.152: 20.17,35.37 20.17,24.81 20.32,24.67 v1(20.32,24.32)
PT21B: length 13.4
  TOP w0.152: v1(20.32,22.72) BGA.E9
  L3_SIGNAL w0.152: v1(20.32,22.72) 19.92,23.12 19.92,35.37
PT22A: length 14.2
  TOP w0.152: v1(20.32,21.92) BGA.F8
  L4_SIGNAL w0.152: v1(20.32,21.92) BGA.F8 19.92,24.72 20.07,24.87 20.07,35.36
PT22B: length 12.7
  TOP w0.152: v1(20.32,23.52) BGA.D9
  L4_SIGNAL w0.152: 20.32,35.36 20.32,25.12 20.72,24.72 BGA.D9 v1(20.32,23.52)
PT22C: length 9.1
  TOP w0.152: v1(20.72,26.89) BGA.A9
  L3_SIGNAL w0.152: v1(20.72,26.89) 20.72,27.33 20.93,27.55 20.93,35.37
PT22D: length 12
  TOP w0.152: v1(21.12,24.32) BGA.C9
  L3_SIGNAL w0.152: 21.19,35.37 21.19,26.69 20.67,26.17 20.67,24.77 v1(21.12,24.32)
PT25A: length 10
  TOP w0.152: 21.19,35.36 21.19,26.67 21.12,26.6 21.12,25.92 BGA.B9
PT25B: length 9.1
  TOP w0.152: 21.45,35.36 21.45,26.67 21.52,26.6 BGA.A10
PT26A: length 13.5
  TOP w0.152: v1(21.12,22.72) BGA.F9
  L4_SIGNAL w0.152: 21.78,35.36 21.78,24.96 21.52,24.7 21.52,23.12 v1(21.12,22.72)
PT26B: length 12.7
  TOP w0.152: v1(22.72,23.52) BGA.E11
  L4_SIGNAL w0.152: v1(22.72,23.52) 22.32,23.92 22.32,24.66 22.03,24.95 22.03,35.36
PT27A: length 12.8
  TOP w0.152: v1(21.12,23.52) BGA.D10
  BOTTOM w0.152: v1(21.12,23.52) 20.72,23.92 20.72,25.51 21.14,25.93 21.14,35.37
PT27B: length 12.6
  TOP w0.152: v1(21.92,23.52) BGA.E10
  BOTTOM w0.152: 21.39,35.37 21.39,25.89 21.52,25.77 21.52,23.92 v1(21.92,23.52)
PT27C: length 11.8
  TOP w0.152: v1(21.92,24.32) BGA.C10
  L3_SIGNAL w0.152: v1(21.92,24.32) 21.72,24.52 21.72,24.74 21.9,24.92 21.9,35.37
PT27D: length 11.6
  TOP w0.152: v1(21.12,25.12) BGA.B10
  L3_SIGNAL w0.152: v1(21.12,25.12) 21.32,24.92 21.54,24.92 21.65,25.03 21.65,35.37
PT28A: length 9.1
  TOP w0.152: 22.25,35.36 22.25,26.82 22.32,26.75 BGA.A11
PT28B: length 10.8
  TOP w0.152: 21.99,35.36 21.99,26.82 21.92,26.75 21.92,25.12 BGA.C11
PT32A: length 13.5
  TOP w0.152: v1(21.92,22.72) BGA.F10
  BOTTOM w0.152: 22.6,35.37 22.6,25.88 22.32,25.6 22.32,23.12 v1(21.92,22.72)
PT32B: length 11.9
  TOP w0.152: v1(22.72,24.32) BGA.D11
  BOTTOM w0.152: 22.85,35.37 22.85,25.89 23.12,25.62 23.12,25.29 23.12,24.72 v1(22.72,24.32)
PT33A: length 10
  TOP w0.152: BGA.B11 22.72,25.92 22.72,26.75 22.79,26.82 22.79,35.36
PT33B: length 9.1
  TOP w0.152: 23.05,35.36 23.05,26.82 23.12,26.75 BGA.A12
PT34A: length 10
  TOP w0.152: 24.39,35.36 24.39,26.82 24.32,26.75 24.32,25.92 BGA.B13
PT34B: length 9.1
  TOP w0.152: 24.65,35.36 24.65,26.82 24.72,26.75 BGA.A14
PT35A: length 11
  TOP w0.152: v1(23.52,25.12) BGA.C12
  L3_SIGNAL w0.152: v1(23.52,25.12) 22.97,25.67 22.97,35.37
PT35B: length 10.8
  TOP w0.152: v1(22.72,25.12) BGA.B12
  L3_SIGNAL w0.152: 22.72,35.37 v1(22.72,25.12)
PT36A: length 10
  TOP w0.152: 25.19,35.36 25.19,26.82 25.12,26.75 25.12,25.92 BGA.B14
PT36B: length 9.1
  TOP w0.152: 25.45,35.36 25.45,26.82 25.52,26.75 BGA.A15
PT36C: length 10.8
  TOP w0.152: v1(23.52,25.92) BGA.A13
  L3_SIGNAL w0.152: 24.22,35.37 24.22,26 23.94,25.72 23.72,25.72 v1(23.52,25.92)
PT36D: length 11
  TOP w0.152: v1(24.32,25.12) BGA.C13
  L3_SIGNAL w0.152: v1(24.32,25.12) 24.12,25.32 24.12,25.54 24.47,25.89 24.47,35.37

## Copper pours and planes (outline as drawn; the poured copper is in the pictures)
GND on L2_GND: 5.42,5.62 5.42,35.74 34.07,35.74 34.07,5.62
VCC on L5_PWR: 29.54,14.73 29.54,24.79 22.63,24.79 22.63,22.05 22.25,21.67 21.82,21.67 21.56,21.92 21.56,23.72 20.5,24.79 16.71,24.79 16.71,23.88 18.08,23.88 19.94,22.02 19.94,20.9 20.07,20.78 20.8,20.78 21.69,19.89 21.95,19.89 22.3,19.53 22.3,18.32 21.72,18.32 20.68,19.36 20.68,19.76 20.55,19.89 20.14,19.89 19.86,19.61 19.86,19.43 19.66,19.23 19.11,19.23 19.07,19.27 19.07,21.42 18.9,21.59 16.79,21.59 16.79,23.14 5.77,23.14 5.77,35.43 33.88,35.43 33.88,5.99 5.77,5.99 5.77,14.73
VCCIO0 on L5_PWR: 20.65,20.88 20.12,20.88 20.07,20.93 20.07,22.1 18.14,24.03 16.87,24.03 16.87,24.66 20.45,24.66 21.44,23.67 21.44,21.87 21.77,21.54 22.33,21.54 22.76,21.97 22.76,24.66 23.85,24.66 23.85,21.31 23.44,20.9 21.97,20.9 21.29,21.59 20.98,21.59 20.65,21.26
VCCIO1 on L5_PWR: 23.98,24.66 23.98,21.23 23.55,20.8 21.89,20.8 21.23,21.46 21.03,21.46 20.78,21.21 20.78,20.96 21.74,19.99 22,19.99 22.4,19.58 22.4,18.31 23.93,16.79 29.44,16.79 29.44,24.66
VCCIO2 on L5_PWR: 5.77,14.86 5.77,17.32 16.87,17.32 16.87,19.13 19.71,19.13 19.96,19.38 19.96,19.56 20.17,19.76 20.52,19.76 20.57,19.71 20.57,19.3 21.66,18.22 22.32,18.22 23.88,16.66 29.44,16.66 29.44,14.86
VCCIO3 on L5_PWR: 16.77,19.13 16.77,17.42 5.77,17.42 5.77,19.13
VCCIO4 on L5_PWR: 5.77,21.46 18.85,21.46 18.97,21.34 18.97,19.23 5.77,19.23
VCCIO5 on L5_PWR: 16.69,23.04 16.69,21.59 5.77,21.59 5.77,23.04

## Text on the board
User.Comments: RCI | RP | 08/06/14 | DWG NO: | XO3L-69E-400caBGA | REVISION | 1.0 | SHEET | 1 | OF | XO3L-69E-400CABGA PCB BREAKOUT | LATTICE SEMICONDUCTOR CORPORATION
Ref Des/Silkscreen Top: PCB BREAKOUT | XO3L-69E-400CABGA | SEMICONDUCTOR | LATTICE | A | B | C | D | E | F | G | H | J | K | L | M | N | P | R | T | 1 | 2 | 3 | 4 | 5 | 6 | 7 | 8 | 9 | 10 | 11 | 12 | 13 | 14 | 15 | 16
PAGE_OUTLINE: 1 | INITIAL RELEASE | MM/DD/YYYY | XXXX XXXXX | SPECIAL INSTRUCTIONS: | 1/2 CU OZ FOR INTERNAL AND EXTERNAL LAYERS | MIN BOARD THICKNESS IS 62MILS. | DESIGNED BY: | APPROVED BY: | SIGNATURES         DATE | REV | DESCRIPTION | ESCAPE VIA DRILL | TRACE WIDTH/SPACE | ESCAPE VIA PAD | ARRAY SIZE | BGA LAND OPENING | BGA LAND PAD | PACKAGE SIZE | PITCH | SIGNAL         (L4) | SIGNAL         (L3) | GND     PLANE  (L2) | POWER   PLANE  (L5) | PRIMARY SIDE   (L1) | SECONDARY SIDE (L6) | SECONDARY SILKSCREEN | SECONDARY SOLDERMASK | PRIMARY SOLDERMASK | PRIMARY SILKSCREEN | 0.15/0.10 | 14 x 14 | 16 x 16 | 0.4064 | 0.4572 | 0.5334 | 0.254 | 0.8 | MM | DATE | 551.18 x 551.18 | 629.92 x 629.92 | 6/4 | 16 | 31.5 | 18 | 10 | 21 | MILS | APPROVED | PCB BREAKOUT DETAILS | 6 LAYER STACKUP | REVISION
BODY_CENTER: FIGURE | SIZE | 10.0 | ALL UNITS ARE IN MILS | SIZE MM | 0.254 | PLATED | QTY | 83 | DRILL CHART: TOP to L4_SIGNAL
PLACE_BOUND_TOP: FIGURE | SIZE | 10.0 | ALL UNITS ARE IN MILS | SIZE MM | 0.254 | PLATED | QTY | 116 | DRILL CHART: TOP to L3_SIGNAL
DISPLAY_TOP: FIGURE | SIZE | 10.0 | ALL UNITS ARE IN MILS | SIZE MM | 0.254 | PLATED | QTY | 50 | DRILL CHART: TOP to BOTTOM
